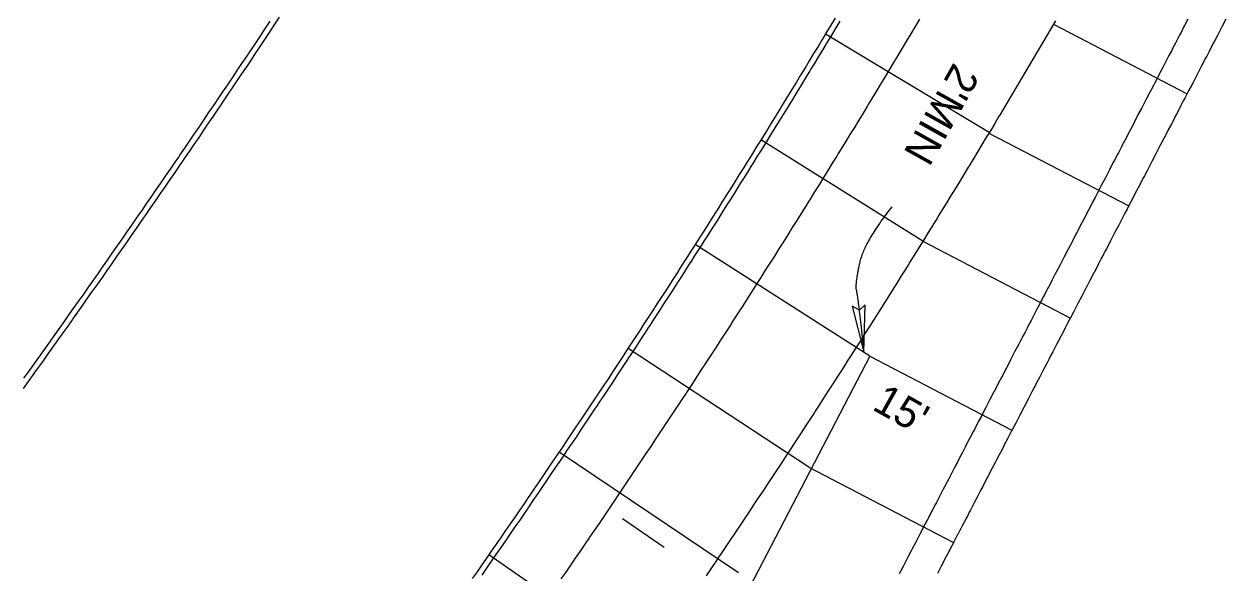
# Model space of a CAD drawing. Extents: x 2145147 to 2158018, y 137519 to 148068.
# Drawn here: x 2150427.2 to 2150569.8, y 143964 to 144029.1 of the extents above; entities that cross this region are included whole.
import ezdxf

# ---------------------------------------------------------------- set-up
doc = ezdxf.new("R2010")
doc.units = 0
for name, color, linetype in [('PR_Align_Ramp_F', 7, 'Continuous'), ('PR_Dimensions', 7, 'Continuous'), ('PR_Joint_Contraction', 7, 'Continuous'), ('PR_Joint_Long', 7, 'Continuous'), ('PR_Phasing_Pavement_1', 7, 'Continuous'), ('PR_Road_Concrete', 7, 'Continuous')]:
    doc.layers.add(name, color=color, linetype=linetype)

msp = doc.modelspace()

# ---------------------------------------------------------------- linework, layer by layer
at = {"layer": 'PR_Align_Ramp_F'}
msp.add_lwpolyline([(2150503.19, 143967.03), (2150498.22, 143970.4)], dxfattribs=at)
at = {"layer": 'PR_Dimensions'}
msp.add_lwpolyline([(2150526.87, 143990.19), (2150527.02, 143995.81), (2150526.34, 143995.15), (2150525.49, 143995.63)], close=True, dxfattribs=at)
msp.add_open_spline([(2150530.19, 144007.44), (2150526.88, 144003.25), (2150525.79, 143998.11), (2150526.14, 143996.98), (2150526.87, 143990.19)], degree=2, dxfattribs=at)
at = {"layer": 'PR_Joint_Contraction'}
for p, q in [((2150549.36, 144029.1), (2150565.22, 144020.85)), ((2150541.73, 144016.23), (2150522.31, 144027.91)), ((2150541.7, 144016.17), (2150558.29, 144007.54)), ((2150533.87, 144003.34), (2150514.66, 144015.37)), ((2150527.59, 143989.7), (2150506.85, 144002.95)), ((2150533.87, 144003.34), (2150551.37, 143994.23)), ((2150520.35, 143976.56), (2150498.89, 143990.63)), ((2150527.59, 143989.7), (2150544.44, 143980.93)), ((2150512, 143963.99), (2150490.72, 143978.34)), ((2150520.36, 143976.55), (2150537.52, 143967.62)), ((2150503.47, 143951.52), (2150482.38, 143966.15))]:
    msp.add_line(p, q, dxfattribs=at)
at = {"layer": 'PR_Joint_Long'}
for points in [[(2150533.46, 144029.67), (2150532.95, 144028.82), (2150532.44, 144027.96), (2150531.93, 144027.1), (2150531.42, 144026.24), (2150530.9, 144025.39), (2150530.89, 144025.36), (2150530.39, 144024.53), (2150529.88, 144023.68), (2150529.36, 144022.82), (2150528.85, 144021.96), (2150528.33, 144021.11), (2150527.81, 144020.26), (2150527.38, 144019.55), (2150527.3, 144019.4), (2150526.78, 144018.55), (2150526.26, 144017.7), (2150525.74, 144016.85), (2150525.22, 144015.99), (2150524.7, 144015.14), (2150524.17, 144014.29), (2150523.84, 144013.75), (2150523.65, 144013.44), (2150523.13, 144012.59), (2150522.6, 144011.74), (2150522.08, 144010.89), (2150521.55, 144010.04), (2150521.03, 144009.2), (2150520.5, 144008.35), (2150520.27, 144007.98), (2150519.97, 144007.5), (2150519.44, 144006.65), (2150518.91, 144005.81), (2150518.38, 144004.96), (2150517.85, 144004.12), (2150517.32, 144003.27), (2150516.79, 144002.43), (2150516.66, 144002.23), (2150516.25, 144001.58), (2150515.72, 144000.74), (2150515.18, 143999.9), (2150514.65, 143999.06), (2150514.11, 143998.21), (2150513.58, 143997.37), (2150513.04, 143996.53), (2150513.02, 143996.5), (2150512.5, 143995.69), (2150511.96, 143994.85), (2150511.42, 143994.01), (2150510.88, 143993.17), (2150510.34, 143992.33), (2150509.8, 143991.49), (2150509.34, 143990.79), (2150509.25, 143990.66), (2150508.71, 143989.82), (2150508.17, 143988.98), (2150508.05, 143988.8), (2150507.62, 143988.15), (2150507.07, 143987.31), (2150506.53, 143986.47), (2150505.98, 143985.64), (2150505.63, 143985.1), (2150505.43, 143984.81), (2150504.88, 143983.97), (2150504.34, 143983.14), (2150503.79, 143982.3), (2150503.23, 143981.47), (2150502.68, 143980.64), (2150502.13, 143979.81), (2150501.89, 143979.44), (2150501.58, 143978.98), (2150501.02, 143978.15), (2150500.47, 143977.32), (2150499.91, 143976.49), (2150499.36, 143975.66), (2150498.8, 143974.83), (2150498.24, 143974), (2150498.11, 143973.8), (2150497.69, 143973.17), (2150497.13, 143972.35), (2150496.57, 143971.52), (2150496.01, 143970.69), (2150495.45, 143969.87), (2150494.89, 143969.04), (2150494.32, 143968.22), (2150494.3, 143968.18), (2150493.76, 143967.39), (2150493.2, 143966.57), (2150492.63, 143965.75), (2150492.07, 143964.92), (2150491.5, 143964.1), (2150490.93, 143963.28)], [(2150549.6, 144029.5), (2150549.09, 144028.63), (2150548.58, 144027.76), (2150548.07, 144026.89), (2150547.56, 144026.02), (2150547.04, 144025.14), (2150546.53, 144024.28), (2150546.41, 144024.07), (2150546.02, 144023.4), (2150545.5, 144022.53), (2150544.99, 144021.67), (2150544.47, 144020.8), (2150543.95, 144019.93), (2150543.43, 144019.06), (2150542.92, 144018.2), (2150542.9, 144018.17), (2150542.4, 144017.33), (2150541.88, 144016.46), (2150541.35, 144015.6), (2150540.83, 144014.73), (2150540.31, 144013.87), (2150539.79, 144013), (2150539.35, 144012.28), (2150539.26, 144012.14), (2150538.74, 144011.27), (2150538.21, 144010.41), (2150537.69, 144009.55), (2150537.16, 144008.69), (2150536.63, 144007.82), (2150536.1, 144006.96), (2150535.77, 144006.42), (2150535.57, 144006.1), (2150535.04, 144005.24), (2150534.51, 144004.38), (2150533.98, 144003.52), (2150533.45, 144002.66), (2150532.92, 144001.81), (2150532.38, 144000.95), (2150532.15, 144000.57), (2150531.85, 144000.09), (2150531.31, 143999.23), (2150530.78, 143998.38), (2150530.24, 143997.52), (2150529.7, 143996.66), (2150529.16, 143995.81), (2150528.63, 143994.96), (2150528.5, 143994.75), (2150528.08, 143994.1), (2150527.54, 143993.25), (2150527, 143992.39), (2150526.46, 143991.54), (2150525.92, 143990.69), (2150525.37, 143989.84), (2150524.83, 143988.99), (2150524.81, 143988.95), (2150524.28, 143988.13), (2150523.74, 143987.28), (2150523.19, 143986.43), (2150522.65, 143985.58), (2150522.1, 143984.74), (2150521.55, 143983.89), (2150521.09, 143983.18), (2150521, 143983.04), (2150520.45, 143982.19), (2150519.9, 143981.35), (2150519.78, 143981.16), (2150519.35, 143980.5), (2150518.79, 143979.65), (2150518.24, 143978.81), (2150517.69, 143977.96), (2150517.33, 143977.42), (2150517.13, 143977.11), (2150516.58, 143976.27), (2150516.02, 143975.43), (2150515.46, 143974.59), (2150514.91, 143973.74), (2150514.35, 143972.9), (2150513.79, 143972.06), (2150513.54, 143971.69), (2150513.23, 143971.22), (2150512.67, 143970.38), (2150512.11, 143969.54), (2150511.55, 143968.7), (2150510.98, 143967.86), (2150510.42, 143967.02), (2150509.86, 143966.18), (2150509.72, 143965.97), (2150509.29, 143965.34), (2150508.73, 143964.5), (2150508.16, 143963.67)], [(2150565.3, 144029.67), (2150564.92, 144028.93), (2150564.81, 144028.73), (2150564.46, 144028.04), (2150564.32, 144027.79), (2150563.99, 144027.16), (2150563.84, 144026.85), (2150563.53, 144026.27), (2150563.35, 144025.91), (2150563.07, 144025.38), (2150562.86, 144024.97), (2150562.61, 144024.5), (2150562.37, 144024.03), (2150562.15, 144023.61), (2150561.88, 144023.09), (2150561.69, 144022.72), (2150561.39, 144022.15), (2150561.22, 144021.83), (2150560.9, 144021.22), (2150560.76, 144020.95), (2150560.41, 144020.28), (2150560.3, 144020.06), (2150559.92, 144019.34), (2150559.84, 144019.17), (2150559.43, 144018.4), (2150559.38, 144018.29), (2150558.94, 144017.46), (2150558.92, 144017.4), (2150558.46, 144016.52), (2150558.45, 144016.51), (2150557.99, 144015.63), (2150557.97, 144015.58), (2150557.53, 144014.74), (2150557.48, 144014.64), (2150557.07, 144013.85), (2150556.99, 144013.7), (2150556.61, 144012.96), (2150556.5, 144012.76), (2150556.15, 144012.08), (2150556.01, 144011.82), (2150555.68, 144011.19), (2150555.52, 144010.88), (2150555.22, 144010.3), (2150555.03, 144009.94), (2150554.76, 144009.42), (2150554.54, 144009), (2150554.3, 144008.53), (2150554.05, 144008.06), (2150553.84, 144007.64), (2150553.57, 144007.12), (2150553.38, 144006.76), (2150553.08, 144006.18), (2150552.91, 144005.87), (2150552.59, 144005.24), (2150552.45, 144004.98), (2150552.1, 144004.3), (2150551.99, 144004.09), (2150551.61, 144003.36), (2150551.53, 144003.21), (2150551.12, 144002.42), (2150551.07, 144002.32), (2150550.63, 144001.48), (2150550.61, 144001.43), (2150550.14, 144000.55), (2150550.14, 144000.54), (2150549.68, 143999.66), (2150549.65, 143999.6), (2150549.58, 143999.46), (2150549.22, 143998.77), (2150549.16, 143998.66), (2150548.76, 143997.88), (2150548.67, 143997.72), (2150548.3, 143997), (2150548.19, 143996.78), (2150547.84, 143996.11), (2150547.7, 143995.84), (2150547.37, 143995.22), (2150547.21, 143994.9), (2150546.91, 143994.34), (2150546.72, 143993.96), (2150546.45, 143993.45), (2150546.23, 143993.03), (2150545.99, 143992.56), (2150545.74, 143992.09), (2150545.53, 143991.68), (2150545.25, 143991.15), (2150545.07, 143990.79), (2150544.76, 143990.21), (2150544.6, 143989.9), (2150544.27, 143989.27), (2150544.14, 143989.01), (2150543.78, 143988.33), (2150543.68, 143988.13), (2150543.3, 143987.39), (2150543.22, 143987.24), (2150542.81, 143986.45), (2150542.76, 143986.35), (2150542.32, 143985.51), (2150542.3, 143985.47), (2150541.83, 143984.58), (2150541.83, 143984.57), (2150541.37, 143983.69), (2150541.34, 143983.63), (2150540.91, 143982.8), (2150540.85, 143982.69), (2150540.45, 143981.92), (2150540.36, 143981.75), (2150539.99, 143981.03), (2150539.87, 143980.81), (2150539.53, 143980.14), (2150539.38, 143979.87), (2150539.06, 143979.26), (2150538.89, 143978.93), (2150538.6, 143978.37), (2150538.4, 143977.99), (2150538.14, 143977.48), (2150537.92, 143977.05), (2150537.68, 143976.6), (2150537.43, 143976.11), (2150537.22, 143975.71), (2150536.94, 143975.17), (2150536.76, 143974.82), (2150536.45, 143974.23), (2150536.29, 143973.93), (2150535.96, 143973.29), (2150535.83, 143973.05), (2150535.6, 143972.6), (2150535.47, 143972.35), (2150535.37, 143972.16), (2150534.98, 143971.41), (2150534.91, 143971.27), (2150534.49, 143970.47), (2150534.45, 143970.39), (2150534, 143969.53), (2150533.99, 143969.5), (2150533.52, 143968.61), (2150533.51, 143968.59), (2150533.06, 143967.72), (2150533.02, 143967.65), (2150532.6, 143966.84), (2150532.54, 143966.71), (2150532.14, 143965.95), (2150532.05, 143965.77), (2150531.68, 143965.06), (2150531.56, 143964.83), (2150531.22, 143964.18), (2150531.07, 143963.9)], [(2150527.59, 143989.7), (2150513.36, 143962.36)]]:
    msp.add_lwpolyline(points, dxfattribs=at)
at = {"layer": 'PR_Phasing_Pavement_1'}
for points in [[(2150427.18, 143985.88), (2150427.77, 143986.7), (2150428.36, 143987.52), (2150428.53, 143987.77), (2150428.95, 143988.35), (2150429.53, 143989.17), (2150430.12, 143989.99), (2150430.7, 143990.81), (2150431.29, 143991.63), (2150431.87, 143992.46), (2150432.46, 143993.28), (2150432.98, 143994.03), (2150433.04, 143994.11), (2150433.62, 143994.93), (2150434.2, 143995.76), (2150434.78, 143996.58), (2150435.37, 143997.41), (2150435.95, 143998.23), (2150436.53, 143999.06), (2150437.1, 143999.89), (2150437.4, 144000.31), (2150437.68, 144000.71), (2150438.26, 144001.54), (2150438.84, 144002.37), (2150439.42, 144003.2), (2150439.99, 144004.03), (2150440.57, 144004.86), (2150441.14, 144005.69), (2150441.72, 144006.52), (2150441.79, 144006.62), (2150442.29, 144007.35), (2150442.86, 144008.18), (2150443.44, 144009.01), (2150444.01, 144009.84), (2150444.58, 144010.67), (2150445.15, 144011.51), (2150445.72, 144012.34), (2150446.14, 144012.95), (2150446.29, 144013.17), (2150446.86, 144014.01), (2150447.43, 144014.84), (2150448, 144015.67), (2150448.56, 144016.51), (2150449.13, 144017.35), (2150449.7, 144018.18), (2150450.26, 144019.02), (2150450.46, 144019.3), (2150450.83, 144019.85), (2150451.39, 144020.69), (2150451.96, 144021.53), (2150452.52, 144022.37), (2150453.08, 144023.2), (2150453.65, 144024.04), (2150454.21, 144024.88), (2150454.74, 144025.68), (2150454.77, 144025.72), (2150455.33, 144026.56), (2150455.89, 144027.4), (2150456.45, 144028.24), (2150457, 144029.08), (2150457.56, 144029.92)], [(2150427.23, 143987.09), (2150427.82, 143987.91), (2150427.99, 143988.16), (2150428.4, 143988.73), (2150428.99, 143989.55), (2150429.57, 143990.38), (2150430.16, 143991.2), (2150430.74, 143992.02), (2150431.33, 143992.84), (2150431.91, 143993.67), (2150432.44, 143994.41), (2150432.49, 143994.49), (2150433.08, 143995.32), (2150433.66, 143996.14), (2150434.24, 143996.96), (2150434.82, 143997.79), (2150435.4, 143998.62), (2150435.98, 143999.44), (2150436.56, 144000.27), (2150436.85, 144000.69), (2150437.14, 144001.1), (2150437.71, 144001.92), (2150438.29, 144002.75), (2150438.87, 144003.58), (2150439.44, 144004.41), (2150440.02, 144005.24), (2150440.59, 144006.07), (2150441.17, 144006.9), (2150441.24, 144007), (2150441.74, 144007.73), (2150442.31, 144008.56), (2150442.89, 144009.39), (2150443.46, 144010.22), (2150444.03, 144011.05), (2150444.6, 144011.88), (2150445.17, 144012.72), (2150445.59, 144013.33), (2150445.74, 144013.55), (2150446.31, 144014.38), (2150446.88, 144015.22), (2150447.44, 144016.05), (2150448.01, 144016.88), (2150448.58, 144017.72), (2150449.14, 144018.56), (2150449.71, 144019.39), (2150449.9, 144019.68), (2150450.27, 144020.23), (2150450.84, 144021.06), (2150451.4, 144021.9), (2150451.96, 144022.74), (2150452.53, 144023.58), (2150453.09, 144024.41), (2150453.65, 144025.25), (2150454.18, 144026.05), (2150454.21, 144026.09), (2150454.77, 144026.93), (2150455.33, 144027.77), (2150455.89, 144028.61), (2150456.45, 144029.45)]]:
    msp.add_lwpolyline(points, dxfattribs=at)
at = {"layer": 'PR_Road_Concrete'}
for points in [[(2150523.45, 144029.81), (2150522.96, 144028.99), (2150522.45, 144028.14), (2150521.94, 144027.29), (2150521.43, 144026.44), (2150520.91, 144025.6), (2150520.4, 144024.75), (2150519.97, 144024.04), (2150519.89, 144023.9), (2150519.37, 144023.05), (2150518.86, 144022.21), (2150518.34, 144021.36), (2150517.82, 144020.52), (2150517.31, 144019.67), (2150516.79, 144018.83), (2150516.46, 144018.29), (2150516.27, 144017.98), (2150515.75, 144017.14), (2150515.23, 144016.3), (2150514.71, 144015.46), (2150514.19, 144014.61), (2150513.66, 144013.77), (2150513.14, 144012.93), (2150512.91, 144012.56), (2150512.62, 144012.09), (2150512.09, 144011.25), (2150511.57, 144010.41), (2150511.04, 144009.57), (2150510.51, 144008.73), (2150509.99, 144007.89), (2150509.46, 144007.05), (2150509.33, 144006.86), (2150508.93, 144006.22), (2150508.4, 144005.38), (2150507.87, 144004.54), (2150507.34, 144003.71), (2150506.8, 144002.87), (2150506.27, 144002.04), (2150505.74, 144001.2), (2150505.72, 144001.17), (2150505.2, 144000.37), (2150504.67, 143999.53), (2150504.13, 143998.7), (2150503.6, 143997.87), (2150503.06, 143997.04), (2150502.52, 143996.2), (2150502.07, 143995.51), (2150501.98, 143995.37), (2150501.44, 143994.54), (2150500.9, 143993.71), (2150500.78, 143993.53), (2150500.36, 143992.88), (2150499.82, 143992.05), (2150499.28, 143991.22), (2150498.73, 143990.39), (2150498.39, 143989.86), (2150498.19, 143989.57), (2150497.65, 143988.74), (2150497.1, 143987.91), (2150496.56, 143987.08), (2150496.01, 143986.26), (2150495.46, 143985.43), (2150494.91, 143984.61), (2150494.67, 143984.24), (2150494.36, 143983.78), (2150493.81, 143982.96), (2150493.26, 143982.13), (2150492.71, 143981.31), (2150492.16, 143980.49), (2150491.61, 143979.67), (2150491.06, 143978.84), (2150490.92, 143978.64), (2150490.5, 143978.02), (2150489.95, 143977.2), (2150489.39, 143976.38), (2150488.84, 143975.56), (2150488.28, 143974.74), (2150487.72, 143973.92), (2150487.16, 143973.1), (2150487.14, 143973.07), (2150486.61, 143972.29), (2150486.05, 143971.47), (2150485.49, 143970.65), (2150484.92, 143969.83), (2150484.36, 143969.02), (2150483.8, 143968.2), (2150483.32, 143967.51), (2150483.24, 143967.39), (2150482.67, 143966.57), (2150482.11, 143965.76), (2150481.54, 143964.95), (2150480.98, 143964.13), (2150480.41, 143963.32)], [(2150524.02, 144029.47), (2150523.53, 144028.65), (2150523.02, 144027.8), (2150522.51, 144026.95), (2150522, 144026.1), (2150521.48, 144025.25), (2150520.97, 144024.4), (2150520.54, 144023.7), (2150520.46, 144023.55), (2150519.94, 144022.71), (2150519.43, 144021.86), (2150518.91, 144021.01), (2150518.39, 144020.17), (2150517.88, 144019.32), (2150517.36, 144018.48), (2150517.03, 144017.94), (2150516.84, 144017.63), (2150516.32, 144016.79), (2150515.8, 144015.95), (2150515.28, 144015.1), (2150514.75, 144014.26), (2150514.23, 144013.42), (2150513.71, 144012.58), (2150513.48, 144012.21), (2150513.18, 144011.74), (2150512.66, 144010.9), (2150512.13, 144010.06), (2150511.61, 144009.22), (2150511.08, 144008.38), (2150510.55, 144007.54), (2150510.02, 144006.7), (2150509.9, 144006.5), (2150509.49, 144005.86), (2150508.96, 144005.02), (2150508.43, 144004.19), (2150507.9, 144003.35), (2150507.37, 144002.51), (2150506.83, 144001.68), (2150506.3, 144000.84), (2150506.28, 144000.81), (2150505.76, 144000.01), (2150505.23, 143999.17), (2150504.69, 143998.34), (2150504.16, 143997.51), (2150503.62, 143996.67), (2150503.08, 143995.84), (2150502.63, 143995.14), (2150502.54, 143995.01), (2150502, 143994.18), (2150501.46, 143993.35), (2150501.34, 143993.17), (2150500.92, 143992.52), (2150500.38, 143991.69), (2150499.84, 143990.86), (2150499.29, 143990.03), (2150498.94, 143989.5), (2150498.75, 143989.2), (2150498.2, 143988.37), (2150497.66, 143987.54), (2150497.11, 143986.72), (2150496.56, 143985.89), (2150496.02, 143985.06), (2150495.47, 143984.24), (2150495.23, 143983.87), (2150494.92, 143983.41), (2150494.37, 143982.59), (2150493.82, 143981.76), (2150493.27, 143980.94), (2150492.72, 143980.12), (2150492.16, 143979.29), (2150491.61, 143978.47), (2150491.47, 143978.27), (2150491.06, 143977.65), (2150490.5, 143976.83), (2150489.94, 143976.01), (2150489.39, 143975.19), (2150488.83, 143974.37), (2150488.27, 143973.55), (2150487.72, 143972.73), (2150487.69, 143972.69), (2150487.16, 143971.91), (2150486.6, 143971.09), (2150486.04, 143970.27), (2150485.47, 143969.46), (2150484.91, 143968.64), (2150484.35, 143967.82), (2150483.87, 143967.13), (2150483.79, 143967.01), (2150483.22, 143966.19), (2150482.66, 143965.38), (2150482.09, 143964.56), (2150481.53, 143963.75)], [(2150569.83, 144029.7), (2150569.39, 144028.86), (2150569.34, 144028.77), (2150568.93, 144027.97), (2150568.85, 144027.82), (2150568.46, 144027.08), (2150568.36, 144026.88), (2150568, 144026.2), (2150567.87, 144025.95), (2150567.54, 144025.31), (2150567.38, 144025.01), (2150567.08, 144024.42), (2150566.89, 144024.07), (2150566.62, 144023.54), (2150566.4, 144023.13), (2150566.16, 144022.65), (2150565.92, 144022.19), (2150565.69, 144021.76), (2150565.43, 144021.25), (2150565.23, 144020.88), (2150564.94, 144020.31), (2150564.77, 144019.99), (2150564.45, 144019.37), (2150564.31, 144019.1), (2150563.96, 144018.43), (2150563.85, 144018.21), (2150563.47, 144017.49), (2150563.39, 144017.33), (2150562.98, 144016.55), (2150562.92, 144016.44), (2150562.49, 144015.61), (2150562.46, 144015.55), (2150562, 144014.67), (2150562, 144014.67), (2150561.54, 144013.78), (2150561.51, 144013.73), (2150561.08, 144012.89), (2150561.02, 144012.79), (2150560.62, 144012), (2150560.54, 144011.85), (2150560.15, 144011.12), (2150560.05, 144010.91), (2150559.69, 144010.23), (2150559.56, 144009.97), (2150559.23, 144009.34), (2150559.07, 144009.03), (2150558.77, 144008.46), (2150558.58, 144008.09), (2150558.31, 144007.57), (2150558.09, 144007.15), (2150557.85, 144006.68), (2150557.6, 144006.21), (2150557.38, 144005.8), (2150557.11, 144005.27), (2150556.92, 144004.91), (2150556.62, 144004.33), (2150556.46, 144004.02), (2150556.13, 144003.39), (2150556, 144003.13), (2150555.65, 144002.45), (2150555.54, 144002.25), (2150555.16, 144001.51), (2150555.08, 144001.36), (2150554.67, 144000.57), (2150554.62, 144000.47), (2150554.18, 143999.63), (2150554.15, 143999.59), (2150553.69, 143998.7), (2150553.69, 143998.69), (2150553.23, 143997.81), (2150553.2, 143997.76), (2150553.13, 143997.62), (2150552.77, 143996.92), (2150552.71, 143996.82), (2150552.31, 143996.04), (2150552.22, 143995.88), (2150551.85, 143995.15), (2150551.73, 143994.94), (2150551.38, 143994.26), (2150551.24, 143994), (2150550.92, 143993.38), (2150550.75, 143993.06), (2150550.46, 143992.49), (2150550.27, 143992.12), (2150550, 143991.6), (2150549.78, 143991.18), (2150549.54, 143990.71), (2150549.29, 143990.24), (2150549.07, 143989.83), (2150548.8, 143989.3), (2150548.61, 143988.94), (2150548.31, 143988.36), (2150548.15, 143988.05), (2150547.82, 143987.42), (2150547.69, 143987.17), (2150547.33, 143986.48), (2150547.23, 143986.28), (2150546.84, 143985.54), (2150546.77, 143985.39), (2150546.35, 143984.6), (2150546.3, 143984.51), (2150545.87, 143983.66), (2150545.84, 143983.62), (2150545.38, 143982.73), (2150545.38, 143982.72), (2150544.92, 143981.85), (2150544.89, 143981.78), (2150544.46, 143980.96), (2150544.4, 143980.84), (2150544, 143980.07), (2150543.91, 143979.9), (2150543.53, 143979.18), (2150543.42, 143978.96), (2150543.07, 143978.3), (2150542.93, 143978.02), (2150542.61, 143977.41), (2150542.44, 143977.08), (2150542.15, 143976.52), (2150541.95, 143976.14), (2150541.69, 143975.63), (2150541.46, 143975.2), (2150541.23, 143974.75), (2150540.97, 143974.26), (2150540.76, 143973.86), (2150540.48, 143973.32), (2150540.3, 143972.97), (2150540, 143972.38), (2150539.84, 143972.09), (2150539.51, 143971.44), (2150539.38, 143971.2), (2150539.15, 143970.75), (2150539.02, 143970.51), (2150538.92, 143970.31), (2150538.53, 143969.57), (2150538.46, 143969.43), (2150538.04, 143968.63), (2150537.99, 143968.54), (2150537.55, 143967.69), (2150537.53, 143967.65), (2150537.07, 143966.77), (2150537.06, 143966.75), (2150536.61, 143965.88), (2150536.57, 143965.81), (2150536.15, 143964.99), (2150536.08, 143964.87), (2150535.69, 143964.1), (2150535.59, 143963.93)]]:
    msp.add_lwpolyline(points, dxfattribs=at)

# ---------------------------------------------------------------- texts
at = {"layer": 'PR_Dimensions'}
for s, rotation, p in [("2'MIN", 240.7623, (2150537.56, 144024.66)), ("15'", 330.7029, (2150527.72, 143983.44))]:
    msp.add_text(s, height=3.6, rotation=rotation, dxfattribs=at).set_placement(p)

doc.saveas('drawing.dxf')
